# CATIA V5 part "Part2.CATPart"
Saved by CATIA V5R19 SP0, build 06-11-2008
Part number: Part2
Bounding box of the stored display mesh (mm): x -15 to 15, y -15 to 15, z 0 to 20
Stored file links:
  D:\Shriniwas\v5_r19\c16_CAT_v5r19\c16_Part\Roll curve Joint\Part2.CATPart
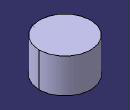
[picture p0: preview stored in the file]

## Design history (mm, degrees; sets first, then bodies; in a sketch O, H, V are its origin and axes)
Body1 (main body)
  Sketch1 on xy-plane, origin (0, 0, 0), H (1, 0, 0), V (0, 1, 0)
    circle A1 centre (0, 0) radius 15
    radius A1 = 15
  Pad1: profile Sketch1, direction (0, 0, 1), length 20
  Point1: type OnCurve, Support edge [face of Pad1 from Sketch1.A1 | end face of Pad1], Length 58.791, RefPoint {extremum Reference edge [face of Pad1 from Sketch1.A1 | end face of Pad1], Direction (1, 2, 3)}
